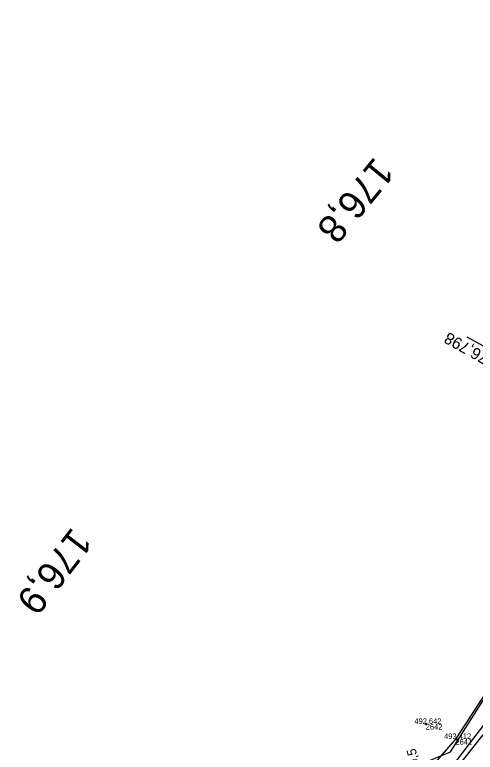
# Model space of a CAD drawing. Extents: x -1234191 to 23050, y -1290331 to -741191.
# Drawn here: x -864892.9 to -864794, y -1102988.9 to -1102830.3 of the extents above; entities that cross this region are included whole.
import ezdxf

# ---------------------------------------------------------------- set-up
doc = ezdxf.new("R2010")
doc.units = 0
for name, color, linetype in [('Vrstva 19', 7, 'Continuous'), ('Vrstva 4', 7, 'Continuous'), ('Vrstva 48', 7, 'Continuous'), ('Vrstva 49', 7, 'Continuous'), ('Vrstva 53', 7, 'Continuous'), ('Vrstva 60', 7, 'Continuous'), ('Vrstva 61', 7, 'Continuous'), ('Vrstva 7', 7, 'Continuous')]:
    doc.layers.add(name, color=color, linetype=linetype)

msp = doc.modelspace()

# ---------------------------------------------------------------- linework, layer by layer
at = {"layer": 'Vrstva 19'}
msp.add_line((-864795.81, -1102899.52), (-864754.27, -1102922.82), dxfattribs=at)
at = {"layer": 'Vrstva 4'}
msp.add_lwpolyline([(-864819.74, -1103021.57), (-864811.27, -1103009.64), (-864802.7, -1102998.29), (-864789.57, -1102981.64)], dxfattribs=at)
at = {"layer": 'Vrstva 49'}
for p, q in [((-864804.36, -1102982.75), (-864804.86, -1102982.81)), ((-864804.64, -1102982.53), (-864804.58, -1102983.03))]:
    msp.add_line(p, q, dxfattribs=at)
for points in [[(-864777.77, -1102954.55), (-864798.22, -1102986.02), (-864803.64, -1102992.31)], [(-864790.81, -1102981.27), (-864803.48, -1102997.71), (-864812.27, -1103009)]]:
    msp.add_lwpolyline(points, dxfattribs=at)
at = {"layer": 'Vrstva 53'}
msp.add_lwpolyline([(-864889.03, -1103323.28), (-864892.77, -1103263.78), (-864892.91, -1103184.37), (-864883.42, -1103119.48), (-864874.29, -1103087.16), (-864855.71, -1103052.53), (-864814.57, -1102995.09), (-864799.32, -1102988.77), (-864779.65, -1102957.8), (-864778.43, -1102951.42), (-864757.64, -1102926.36), (-864755.77, -1102924.22), (-864753.95, -1102921.47), (-864728.77, -1102872.58), (-864694.07, -1102830.31)], dxfattribs=at)
at = {"layer": 'Vrstva 60'}
for p, q in [((-864804.61, -1102982.78), (-864804.61, -1102982.78)), ((-864798.22, -1102986.02), (-864798.22, -1102986.02))]:
    msp.add_line(p, q, dxfattribs=at)

# ---------------------------------------------------------------- texts
at = {"layer": 'Vrstva 19'}
msp.add_text('evid. km 176,798', height=2.5, rotation=150.7186, dxfattribs=at).set_placement((-864777.51, -1102910.9))
at = {"layer": 'Vrstva 48'}
msp.add_text('0,5', height=2, rotation=102.6835, dxfattribs=at).set_placement((-864805.99, -1102991.53))
at = {"layer": 'Vrstva 60'}
for s, p in [('2642', (-864804.61, -1102983.98)), ('2641', (-864798.22, -1102987.22))]:
    msp.add_text(s, height=1.2, dxfattribs=at).set_placement(p)
at = {"layer": 'Vrstva 61'}
for s, p in [('492.642', (-864807.06, -1102982.78)), ('493.412', (-864800.67, -1102986.02))]:
    msp.add_text(s, height=1.2, dxfattribs=at).set_placement(p)
at = {"layer": 'Vrstva 7'}
for s, rotation, p in [('176,8', 230.6467, (-864815.58, -1102860.63)), ('176,9', 232.5178, (-864880.58, -1102940.23))]:
    msp.add_text(s, height=6, rotation=rotation, dxfattribs=at).set_placement(p)

doc.saveas('drawing.dxf')
